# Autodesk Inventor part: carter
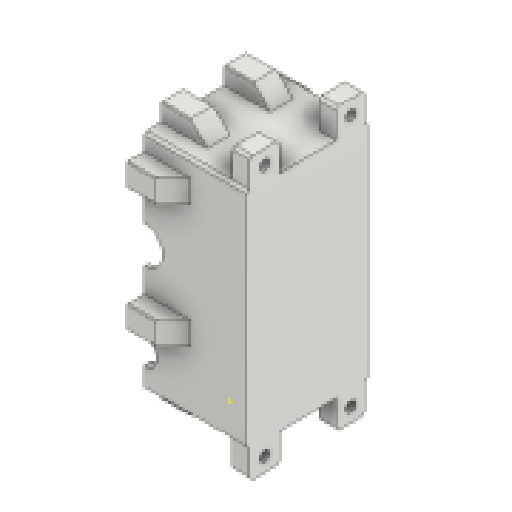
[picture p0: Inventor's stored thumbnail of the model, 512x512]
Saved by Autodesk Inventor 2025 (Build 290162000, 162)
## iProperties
Created: 2026-05
Part Number: carter
Material: Acciaio
Document SubType Name: Modeling
Designer: R5800u
Density: 7.85 g/cm^3
Appearance: Acciaio
Author: R5800u
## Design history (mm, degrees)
node "Piano di lavoro1"
sketch "Schizzo1"
  geometry: L1 (0, -58)-(160, -58); L2 (160, -58)-(160, 332); L3 (160, 332)-(0, 332); L4 (0, 332)-(0, -58); C1 r 12 at (0, 0) reference; C2 r 31 at (0, 0) reference; C3 r 45 at (0, 162) reference; A1 r 19.5 centre (0, 162) between (-18.561, 156.023) and (-18.547, 168.023) reference; 5 further points
  constraints: 8 end point, 2 parallel, 1 horizontal, 1 perpendicular
  dimensions: "d0" = 160 distance of L1.start L1.end; "d1" = 390 distance of L1.end L2.end
extrude "Estrusione1" new body sketch "Schizzo1" distance "d3" = 35; taper "d4" = 0 deg
node "Piano di lavoro2"
mirror "Speculare1"
sketch "Schizzo2"
  geometry: L1 (0, 390)-(35, 390) reference; L2 (210, 0)-(210, 390) reference; L3 (0, 390)-(210, 390); L4 (210, 390)-(210, 0); L5 (210, 0)-(0, 0); L6 (0, 0)-(0, 390); 3 further points
  constraints: 8 end point, 2 parallel, 1 horizontal, 1 perpendicular
extrude "Estrusione2" join sketch "Schizzo2" distance "d6" = 20; taper "d7" = 0 deg
sketch "Schizzo3"
  geometry: L1 (-175, 390)-(-35, 390) reference; L2 (-175, 390)-(-175, 0) reference; L3 (-35, 390)-(-175, 390); L4 (-175, 390)-(-175, 370); L5 (-175, 370)-(-35, 370); L6 (-35, 370)-(-35, 390); L7 (0, 0)-(-35, 0) reference; L8 (-35, 0)-(-175, 0); L9 (-175, 0)-(-175, 20); L10 (-175, 20)-(-35, 20); L11 (-35, 20)-(-35, 0); 2 further points
  constraints: 16 end point, 4 parallel, 2 horizontal, 2 perpendicular, 2 point on line
  dimensions: "d8" = 20 distance of L4.end L3.end; "d9" = 20 distance of L8.end L9.end
extrude "Estrusione3" join sketch "Schizzo3" stored distance "d10" = 20; taper "d11" = 0 deg
sketch "Schizzo4"
  geometry: L1 (0, 170)-(0, 45) reference; L2 (0, 170)-(-180, 170) reference; L3 (-180, -220)-(-180, 170) reference; L4 (0, -220)-(-180, -220) reference; L5 (0, -193)-(0, -220) reference; L6 (0, -45)-(0, -131) reference; L7 (0, 45)-(0, -45); C1 r 32.5 at (0, 0); A1 r 31 centre (0, -162) between (0, -131) and (0, -193) reference; A2 r 45 centre (0, 0) between (0, 45) and (0, -45) reference; 3 further points
  constraints: 2 end point, 1 centre point, 1 coincident, 1 vertical
  dimensions: "d12" = 65 diameter of C1
  node "Linea chiusa proiettata1"
node "Piano di lavoro3"
extrude "Estrusione4" join sketch "Schizzo4" stored distance "d13" = 10; taper "d14" = 0 deg
sketch "Schizzo5"
  geometry: L1 (0, 332)-(0, 194.5) reference; L2 (0, 332)-(-180, 332) reference; L3 (-180, -58)-(-180, 332) reference; L4 (0, -58)-(-180, -58) reference; L5 (0, -31)-(0, -58) reference; L6 (0, 31)-(0, 129.5) reference; L7 (0, 31)-(0, -31); C1 r 21 at (-1.789, 0); A1 r 31 centre (0, 0) between (0, 31) and (0, -31) reference; A2 r 32.5 centre (0, 162) between (0, 194.5) and (0, 129.5) reference; 3 further points
  constraints: 2 end point, 1 centre point, 1 collinear
  dimensions: "d15" = 42 diameter of C1
  node "Linea chiusa proiettata2"
node "Piano di lavoro4"
extrude "Estrusione5" join sketch "Schizzo5" stored distance "d16" = 10; taper "d17" = 0 deg
mirror "Speculare2"
chamfer "Smusso1" distance "d18" = 5; stored, may be unused: second distance "d19" = 2, angle "d20" = 45 deg
sketch "Schizzo6"
  geometry: L1 (-35, 120)-(-30, 125) reference; L2 (-35, 120)-(-35, -12.5) reference; L3 (-35, -12.5)-(-28, -12.5) reference; L4 (-28, 0)-(-28, -12.5) reference; L5 (-28, 0)-(0, 0) reference; L6 (0, 0)-(0, 105) reference; L7 (140, 105)-(0, 105) reference; L8 (140, 0)-(140, 105) reference; L9 (168, 0)-(140, 0) reference; L10 (168, 0)-(168, -12.5) reference; L11 (175, -12.5)-(168, -12.5) reference; L12 (175, 120)-(175, -12.5) reference; L13 (170, 125)-(175, 120) reference; L14 (170, 125)-(-30, 125) reference; L15 (175, -260)-(170, -265) reference; L16 (175, -227.924)-(175, -260) reference; L17 (175, -227.924)-(162, -227.924) reference; L18 (162, -227.924)-(162, -238) reference; L19 (162, -238)-(140, -238) reference; L20 (140, -245)-(140, -238) reference; L21 (0, -245)-(140, -245) reference; L22 (0, -245)-(0, -238) reference; L23 (-22, -238)-(0, -238) reference; L24 (-22, -227.924)-(-22, -238) reference; L25 (-35, -227.924)-(-22, -227.924) reference; L26 (-35, -260)-(-35, -227.924) reference; L27 (-30, -265)-(-35, -260) reference; L28 (170, -265)-(-30, -265) reference; L29 (175, -77.5)-(175, -186.076) reference; L30 (175, -77.5)-(168, -77.5) reference; L31 (168, -77.5)-(168, -90) reference; L32 (168, -90)-(140, -90) reference; L33 (140, -176)-(140, -90) reference; L34 (162, -176)-(140, -176) reference; L35 (162, -176)-(162, -186.076) reference; L36 (175, -186.076)-(162, -186.076) reference; L37 (-35, -186.076)-(-35, -77.5) reference; L38 (-35, -186.076)-(-22, -186.076) reference; L39 (-22, -176)-(-22, -186.076) reference; L40 (-22, -176)-(0, -176) reference; L41 (0, -176)-(0, -90) reference; L42 (-28, -90)-(0, -90) reference; L43 (-28, -77.5)-(-28, -90) reference; L44 (-35, -77.5)-(-28, -77.5) reference; L45 (125, 125)-(125, -265); L46 (-30, 125)-(170, 125) reference; L47 (70, 125)-(70, -265); L48 (15, 125)-(15, -265); L49 (175, 75)-(-35, 75); L50 (-35, -260)-(-35, 120) reference; L51 (145, 95)-(205, 95); L52 (205, 95)-(205, 55); L53 (205, 55)-(145, 55); L54 (145, 55)-(145, 95); L55 (145, 95)-(205, 55); L56 (205, 95)-(145, 55); L57 (145, -235)-(105, -235); L58 (105, -235)-(105, -295); L59 (105, -295)-(145, -295); L60 (145, -295)-(145, -235); L61 (145, -235)-(105, -295); L62 (105, -235)-(145, -295); L63 (35, -235)-(-5, -235); L64 (-5, -235)-(-5, -295)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; 16 further points
  constraints: 106 end point, 18 midpoint, 16 parallel, 11 perpendicular, 8 horizontal, 6 point on line, 2 symmetric about line
  dimensions: "d21" = 50 distance between parallel lines of L12 L45; "d22" = 50 distance between parallel lines of L14 L49; "d23" = 60 distance of L52.end L53.end; "d24" = 40 distance of L51.end L52.end; "d29" = 40 distance of L59.end L58.end; "d30" = 60 distance of L58.end L57.end; "d31" = 40 distance of L65.end L64.end; "d32" = 60 distance of L64.end L63.end; "d33" = 40 distance of L71.end L70.end; "d34" = 60 distance of L70.end L69.end; "d35" = 60 distance of L77.end L76.end; "d36" = 40 distance of L76.end L75.end; "d41" = 40 distance of L83.end L82.end; "d42" = 60 distance of L82.end L81.end; "d43" = 60 distance of L90.end L91.end; "d44" = 40 distance of L89.end L90.end; "d45" = 60 distance of L97.end L96.end; "d46" = 40 distance of L96.end L95.end; "d47" = 125 distance between parallel lines of L28 L88
extrude "Estrusione6" join sketch "Schizzo6" distance "d48" = 50; taper "d49" = 0 deg
chamfer "Smusso2" distance "d50" = 30; stored, may be unused: second distance "d51" = 2, angle "d52" = 45 deg
sketch "Schizzo7"
  geometry: L1 (-35, 120)-(-30, 125) reference; L2 (-35, 120)-(-35, 95) reference; L3 (-35, 95)-(-65, 95) reference; L4 (-65, 95)-(-65, 55) reference; L5 (-65, 55)-(-35, 55) reference; L6 (-35, 55)-(-35, -12.5) reference; L7 (-35, -12.5)-(-28, -12.5) reference; L8 (-28, 0)-(-28, -12.5) reference; L9 (-28, 0)-(0, 0) reference; L10 (0, 0)-(0, 105) reference; L11 (140, 105)-(0, 105) reference; L12 (140, 0)-(140, 105) reference; L13 (168, 0)-(140, 0) reference; L14 (168, 0)-(168, -12.5) reference; L15 (175, -12.5)-(168, -12.5) reference; L16 (175, 55)-(175, -12.5) reference; L17 (175, 55)-(205, 55) reference; L18 (205, 55)-(205, 95) reference; L19 (205, 95)-(175, 95) reference; L20 (175, 120)-(175, 95) reference; L21 (170, 125)-(175, 120) reference; L22 (170, 125)-(145, 125) reference; L23 (145, 125)-(145, 155) reference; L24 (145, 155)-(105, 155) reference; L25 (105, 155)-(105, 125) reference; L26 (105, 125)-(35, 125) reference; L27 (35, 125)-(35, 155) reference; L28 (35, 155)-(-5, 155) reference; L29 (-5, 155)-(-5, 125) reference; L30 (-5, 125)-(-30, 125) reference; L31 (-35, -186.076)-(-35, -160) reference; L32 (-35, -186.076)-(-22, -186.076) reference; L33 (-22, -176)-(-22, -186.076) reference; L34 (-22, -176)-(0, -176) reference; L35 (0, -176)-(0, -90) reference; L36 (-28, -90)-(0, -90) reference; L37 (-28, -77.5)-(-28, -90) reference; L38 (-35, -77.5)-(-28, -77.5) reference; L39 (-35, -120)-(-35, -77.5) reference; L40 (-35, -120)-(-65, -120) reference; L41 (-65, -120)-(-65, -160) reference; L42 (-65, -160)-(-35, -160) reference; L43 (-5, -265)-(35, -265) reference; L44 (175, -260)-(170, -265) reference; L45 (175, -227.924)-(175, -260) reference; L46 (175, -227.924)-(162, -227.924) reference; L47 (162, -227.924)-(162, -238) reference; L48 (162, -238)-(140, -238) reference; L49 (140, -245)-(140, -238) reference; L50 (0, -245)-(140, -245) reference; L51 (0, -245)-(0, -238) reference; L52 (-22, -238)-(0, -238) reference; L53 (-22, -227.924)-(-22, -238) reference; L54 (-35, -227.924)-(-22, -227.924) reference; L55 (-35, -260)-(-35, -227.924) reference; L56 (-30, -265)-(-35, -260) reference; L57 (-5, -265)-(-30, -265) reference; L58 (-5, -265)-(-5, -295) reference; L59 (-5, -295)-(35, -295) reference; L60 (35, -295)-(35, -265) reference; L61 (105, -265)-(35, -265) reference; L62 (105, -265)-(105, -295) reference; L63 (105, -295)-(145, -295) reference; L64 (145, -295)-(145, -265) reference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; 9 further points
  constraints: 16 end point, 8 midpoint, 2 parallel
hole "Foro1" sketch "Schizzo7" at (15, -280), (125, -280), (190, -140), (-50, -140), (-50, 75), (15, 140), (125, 140), (190, 75) diameter "d53" = 10.106; stored, may be unused: countersink angle "d57" = 82 deg, drill point angle "d59" = 118 deg; dims "d54" = 24, "d55" = 3.023, "d56" = 2, "d58" = 32.3
sketch "Schizzo8"
  geometry: L1 (160, 30)-(160, 170) reference; L2 (160, 100)-(144, 100); 1 further point
  constraints: 2 end point, 1 horizontal, 1 midpoint
  dimensions: "d60" = 16 distance of L2.start L2.end
hole "Foro2" sketch "Schizzo8" at (144, 100) diameter "d61" = 29.83494; stored, may be unused: countersink angle "d65" = 90 deg, drill point angle "d67" = 118 deg; dims "d62" = 64, "d63" = 4, "d64" = 2, "d66" = 73.3
chamfer "Smusso3" distance "d68" = 2; stored, may be unused: second distance "d69" = 2, angle "d70" = 45 deg
chamfer "Smusso4" distance "d71" = 0.4; stored, may be unused: second distance "d72" = 2, angle "d73" = 45 deg
sketch "Schizzo9"
  geometry: L1 (205, 390)-(210, 385) reference; L2 (205, 390)-(5, 390) reference; L3 (0, 385)-(5, 390) reference; L4 (0, 385)-(0, 5) reference; L5 (5, 0)-(0, 5) reference; L6 (5, 0)-(205, 0) reference; L7 (210, 5)-(205, 0) reference; L8 (210, 5)-(210, 385) reference; L9 (205, 0)-(155, 0); L10 (155, 0)-(155, -50); L11 (155, -50)-(205, -50); L12 (205, -50)-(205, 0); L13 (5, 0)-(55, 0); L14 (55, 0)-(55, -50); L15 (55, -50)-(5, -50); L16 (5, -50)-(5, 0); L17 (205, 390)-(155, 390); L18 (155, 390)-(155, 440); L19 (155, 440)-(205, 440); L20 (205, 440)-(205, 390); L21 (5, 390)-(55, 390); L22 (55, 390)-(55, 440); L23 (55, 440)-(5, 440); L24 (5, 440)-(5, 390); 5 further points
  constraints: 32 end point, 8 parallel, 4 horizontal, 4 perpendicular, 2 point on line
  dimensions: "d74" = 50 distance of L11.end L10.end; "d75" = 50 distance of L10.end L9.end; "d76" = 50 distance of L18.end L19.end; "d77" = 50 distance of L17.end L18.end; "d78" = 50 distance of L23.end L22.end; "d79" = 50 distance of L22.end L21.end
extrude "Estrusione7" join sketch "Schizzo9" distance "d80" = 30; taper "d81" = 0 deg
sketch "Schizzo10"
  geometry: 1 further point
sketch "Schizzo11"
  geometry: L1 (-205, 0)-(-205, -50) reference; L2 (-205, -50)-(-155, -50) reference; L3 (-155, -50)-(-155, 0) reference; L4 (-205, 0)-(-155, 0) reference; L5 (-155, 440)-(-205, 440) reference; L6 (-205, 440)-(-205, 390) reference; L7 (-155, 390)-(-205, 390) reference; L8 (-155, 390)-(-155, 440) reference; L9 (-5, 390)-(-5, 440) reference; L10 (-5, 440)-(-55, 440) reference; L11 (-55, 440)-(-55, 390) reference; L12 (-5, 390)-(-55, 390) reference; L13 (-55, -50)-(-5, -50) reference; L14 (-5, -50)-(-5, 0) reference; L15 (-55, 0)-(-5, 0) reference; L16 (-55, 0)-(-55, -50) reference; L17 (-205, 0)-(-155, -50); L18 (-55, -50)-(-5, 0); L19 (-155, 440)-(-205, 390); L20 (-55, 440)-(-5, 390); 5 further points
  constraints: 8 end point, 4 midpoint, 2 perpendicular, 1 parallel
hole "Foro3" sketch "Schizzo11" at (-180, -25), (-30, -25), (-180, 415), (-30, 415) diameter "d85" = 17.294; stored, may be unused: countersink angle "d89" = 90 deg, drill point angle "d91" = 118 deg; dims "d86" = 40, "d87" = 32, "d88" = 10, "d90" = 8
chamfer "Smusso6" distance "d92" = 5; stored, may be unused: second distance "d93" = 2, angle "d94" = 45 deg
node "Solido1"
node "Riferimento1"
node "Riferimento2"
node "Riferimento3"
node "Riferimento4"
node "Linea chiusa proiettata3"
node "Linea chiusa proiettata4"
node "Linea chiusa proiettata5"
node "Linea chiusa proiettata6"
node "Linea chiusa proiettata7"
node "Linea chiusa proiettata8"
node "Linea chiusa proiettata9"
node "Linea chiusa proiettata10"
node "Linea chiusa proiettata11"
node "Linea chiusa proiettata12"
node "Linea chiusa proiettata13"
node "Linea chiusa proiettata14"
node "Linea chiusa proiettata15"
